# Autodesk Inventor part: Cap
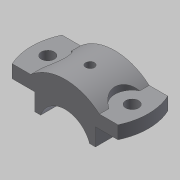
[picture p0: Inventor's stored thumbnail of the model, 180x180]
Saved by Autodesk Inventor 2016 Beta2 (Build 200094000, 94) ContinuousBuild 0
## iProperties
Created: 2009-04
Part Number: Cap
Document SubType Name: Modeling
Designer: Sham
Density: 1 g/cm^3
Material: Generic
Appearance: Default
Author: Sham
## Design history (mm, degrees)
sketch "Sketch1"
  geometry: L1 (-48.857, 23)-(48.857, 23); L2 (48.857, -23)-(-48.857, -23); A1 r 54 centre (0, 0) between (-48.857, 23) and (-48.857, -23); A2 r 54 centre (0, 0) between (48.857, -23) and (48.857, 23); 1 further point
  constraints: 4 end point, 4 point on circle, 2 centre point, 2 coincident, 1 horizontal, 1 parallel, 1 other
  dimensions: "d3" = 54 radius of A1; "d4" = 54 radius of A2; "d5" = 46 distance between parallel lines of L2 L1; "d6" = 23 distance from line of point (0, 0) L1
extrude "Extrusion1" new body sketch "Sketch1" distance "d7" = 12; taper "d8" = 0 deg
sketch "Sketch3"
  geometry: L1 (20.906, 0)-(20.906, -16); L2 (76.906, -0.137)-(76.906, -16.137); L3 (20.906, -16)-(26.23, -16); L4 (71.532, -16.137)-(76.906, -16.137); L5 (76.906, -0.137)-(76.857, 12); L6 (97.714, 0)-(0, 0) reference; L7 (76.857, 12)-(80.606, 12); L8 (17.108, 12)-(20.906, 12); L9 (20.906, 12)-(20.906, 0); L10 (0, 12)-(97.714, 12) reference; A1 r 24 centre (48.857, -24) between (71.532, -16.137) and (26.23, -16); A2 r 48 centre (48.857, -24) between (80.606, 12) and (17.108, 12); 3 further points
  constraints: 16 end point, 4 point on circle, 3 parallel, 3 perpendicular, 2 centre point, 2 coincident, 2 vertical alignment, 1 collinear, 1 midpoint, 1 vertical, 2 other
  dimensions: "d17" = 48 diameter of A1; "d18" = 16 distance of L1.start L1.end; "d19" = 56 distance between parallel lines of L2 L1; "d21" = 8 vertical distance of A1.centre L1.end; "d22" = 48 radius of A2; "d23" = 0 distance from line of L6 L1.start; "d38" = 31.74902 distance of L7.end point (48.857, 12); "d39" = 28 distance from line of point (48.857, 12) L5
extrude "Extrusion2" join sketch "Sketch3" stored distance "d24" = 12; taper "d25" = 0 deg
sketch "Sketch4"
  geometry: 2 further points
  dimensions: "d26" = 78 distance of point (39, 0) point (-39, 0)
hole "Hole1" sketch "Sketch4" at (-39, 0), (39, 0) diameter "d28" = 12; stored, may be unused: countersink angle "d32" = 90 deg, drill point angle "d34" = 118 deg; dims "d29" = 6, "d30" = 4, "d31" = 2, "d33" = 8
sketch "Sketch5"
  geometry: L1 (-31.749, -23)-(-31.749, 23) reference; L2 (-31.749, 14.263)-(-31.749, -14.263); C1 r 6 at (-39, 0) reference; A1 r 16 centre (-39, 0) between (-31.749, -14.263) and (-31.749, 14.263)
  constraints: 2 end point, 2 point on circle, 1 centre point, 1 coincident, 1 collinear, 1 point on line
  dimensions: "d35" = 16 radius of A1
extrude "Extrusion3" cut sketch "Sketch5" distance "d36" = 12; taper "d37" = 0 deg
mirror "Mirror2"
workplane "Work Plane4"
sketch "Sketch6"
  geometry: L1 (-31.749, 0)-(31.749, 0) reference; 1 further point
  dimensions: "d40" = 23 distance from line of L1 point (0, 23)
hole "Hole2" sketch "Sketch6" at (0, 23) diameter "d41" = 6; stored, may be unused: countersink angle "d45" = 90 deg, drill point angle "d47" = 118 deg; dims "d42" = 6, "d43" = 8, "d44" = 16, "d46" = 8
body "Solid1"
